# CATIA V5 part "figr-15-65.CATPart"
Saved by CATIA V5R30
Part number: Part1
Bounding box of the stored display mesh (mm): x -92.936 to 49.742, y -31.904 to 31.904, z 0 to 63.808
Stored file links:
  D:\PROJECTS\CATIA V56R 2020\Resources\Parts File\c15_catia_v5_6r2020_prt\figr-15-65.CATPart
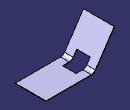
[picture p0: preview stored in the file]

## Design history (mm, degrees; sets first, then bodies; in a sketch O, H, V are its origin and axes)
SheetMetalParameters1: Thickness 1, BendRadius 10, KFactor 0.5 {= log(min(100,max(20*SheetMetalParameters1.BendRadius,SheetMetalParameters1.Thickness)/SheetMetalParameters1.Thickness))/log(100)/2}, ReliefRadialLength 1, ReliefAxialLength 2, MinimumBendRadius 0
Body1 (main body)
  Sketch1 on xy-plane, origin (0, 0, 0), H (1, 0, 0), V (0, 1, 0)
    line L1 (49.7419, 31.9042) -> (49.7419, -31.9042)
    line L2 (49.7419, -31.9042) -> (-49.7419, -31.9042)
    line L3 (-49.7419, -31.9042) -> (-49.7419, 31.9042)
    line L4 (-49.7419, 31.9042) -> (49.7419, 31.9042)
    vertical: L1 V, L3 V
    horizontal: L2 H, L4 H
    equidistance: L1 L3 O, L2 L4 O
  Wall1: Thickness 1, Profile Sketch1
  d_NewWallOnEdge1: NewWallOnEdge_Edge edge [face of Wall1 | face of Wall1], NewWallOnEdge_Length 63.8083, NewWallOnEdge_HeightLimitOffset 0, NewWallOnEdge_WidthOffset1 0, NewWallOnEdge_WidthOffset2 0, NewWallOnEdge_Angle 124, NewWallOnEdge_BendRadiusValue 10 {= SheetMetalParameters1.BendRadius}, NewWallOnEdge_BendTable SheetMetalParameters1, KFacteur 0.5 {= log(min(100,max(20*d_NewWallOnEdge1.Radius,SheetMetalParameters1.Thickness)/SheetMetalParameters1.Thickness))/log(100)/2}
  Sketch2 on face of d_NewWallOnEdge1, origin (0, 0, 1), H (1, 0, 0), V (0, 1, 0)
    point P1 (-49.1841, 0)
    line L1 (-30.5497, 14.1437) -> (-30.5497, -14.1437)
    line L2 (-30.5497, -14.1437) -> (-67.8185, -14.1437)
    line L3 (-67.8185, -14.1437) -> (-67.8185, 14.1437)
    line L4 (-67.8185, 14.1437) -> (-30.5497, 14.1437)
    coincidence: P1 H
    vertical: L1 V, L3 V
    horizontal: L2 H, L4 H
    equidistance: L1 L3 P1, L2 L4 P1
  CutOut1: Direction Sketch2, EndLimit through (limit type 2), Orientation true, Profile Sketch2, StartLimit through (limit type 2)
